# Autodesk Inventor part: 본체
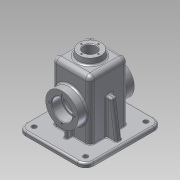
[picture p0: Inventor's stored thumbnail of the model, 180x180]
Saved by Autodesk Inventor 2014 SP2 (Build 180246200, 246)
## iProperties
Created: 2016-08
Part Number: 본체
Material: 알루미늄 6061
Document SubType Name: Modeling
Designer: user
Density: 2.71 g/cm^3
Appearance: 알루미늄 - 평지
Mass: 796.489 g
Surface Area: 912.85 cm^2
Volume: 293.907 cm^3
Author: user
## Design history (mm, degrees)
sketch "스케치1"
  geometry: L1 (-57.5, 65)-(57.5, 65); L2 (57.5, 65)-(57.5, -65); L3 (57.5, -65)-(-57.5, -65); L4 (-57.5, -65)-(-57.5, 65); L5 (-57.5, 65)-(57.5, -65); L6 (57.5, 65)-(-57.5, -65); 1 further point
  constraints: 12 end point, 2 midpoint, 2 parallel, 1 horizontal, 1 perpendicular
  dimensions: "d0" = 115 distance of L2.end L3.end; "d1" = 130 distance of L1.end L2.end
extrude "돌출1" new body sketch "스케치1" distance "d2" = 7; taper "d3" = 0 deg
fillet "모깎기1" dims "d4" = 14
sketch "스케치2"
  geometry: L1 (43.5, 65)-(-43.5, 65) reference; L2 (-57.5, 51)-(-57.5, -51) reference; L3 (-43.5, -65)-(43.5, -65) reference; L4 (57.5, -51)-(57.5, 51) reference; L5 (43.5, -60)-(-43.5, -60); L6 (-52.5, -51)-(-52.5, 51); L7 (-43.5, 60)-(43.5, 60); L8 (52.5, 51)-(52.5, -51); A1 r 14 centre (43.5, 51) between (57.5, 51) and (43.5, 65) reference; A2 r 14 centre (-43.5, 51) between (-43.5, 65) and (-57.5, 51) reference; A3 r 14 centre (-43.5, -51) between (-57.5, -51) and (-43.5, -65) reference; A4 r 14 centre (43.5, -51) between (43.5, -65) and (57.5, -51) reference; A5 r 9 centre (-43.5, -51) between (-52.5, -51) and (-43.5, -60); A6 r 9 centre (-43.5, 51) between (-43.5, 60) and (-52.5, 51); A7 r 9 centre (43.5, 51) between (52.5, 51) and (43.5, 60); A8 r 9 centre (43.5, -51) between (43.5, -60) and (52.5, -51); 1 further point
  constraints: 8 end point, 8 point on circle, 4 centre point, 7 other
  dimensions: "d5" = 5 distance between parallel lines of L5 L3
extrude "돌출2" join sketch "스케치2" distance "d6" = 3; taper "d7" = 0 deg
sketch "스케치3"
  geometry: L1 (-32.5, 32.5)-(32.5, 32.5); L2 (32.5, 32.5)-(32.5, -32.5); L3 (32.5, -32.5)-(-32.5, -32.5); L4 (-32.5, -32.5)-(-32.5, 32.5); L5 (-32.5, 32.5)-(32.5, -32.5); L6 (32.5, 32.5)-(-32.5, -32.5); 1 further point
  constraints: 12 end point, 2 midpoint, 2 parallel, 1 horizontal, 1 perpendicular
  dimensions: "d8" = 65 distance of L2.end L3.end; "d9" = 65 distance of L1.end L2.end
extrude "돌출3" join sketch "스케치3" distance "d10" = 100; taper "d11" = 0 deg
fillet "모깎기2" dims "d12" = 8
fillet "모깎기3" dims "d13" = 8
sketch "스케치4"
  geometry: L1 (-24.5, 107)-(24.5, 107) reference; L2 (-32.5, 7)-(-32.5, 99) reference; L3 (32.5, 99)-(32.5, 7) reference; L4 (27.5, -3)-(27.5, 99); L5 (24.5, 102)-(-24.5, 102); L6 (-27.5, 99)-(-27.5, -3); L7 (-51, -3)-(51, -3) reference; A1 r 8 centre (-24.5, 99) between (-24.5, 107) and (-32.5, 99) reference; A2 r 8 centre (24.5, 99) between (32.5, 99) and (24.5, 107) reference; A3 r 3 centre (24.5, 99) between (27.5, 99) and (24.5, 102); A4 r 3 centre (-24.5, 99) between (-24.5, 102) and (-27.5, 99); 1 further point
  constraints: 6 end point, 4 point on circle, 2 centre point, 2 point on line, 2 other
  dimensions: "d14" = 5 distance between parallel lines of L5 L1; "d15" = 5 distance between parallel lines of L6 L2; "d16" = 5 distance between parallel lines of L3 L4
extrude "돌출4" cut sketch "스케치4" stored distance "d17" = 55; taper "d18" = 0 deg
fillet "모깎기4" dims "d19" = 3
sketch "스케치5"
  geometry: L1 (68, -10)-(-19, -10) reference; C1 r 27.5 at (24.5, 45); 2 further points
  constraints: 1 centre point, 1 midpoint, 1 vertical alignment
  dimensions: "d20" = 55 diameter of C1; "d21" = 55 distance from line of L1 C1.centre
extrude "돌출5" join sketch "스케치5" distance "d22" = 15; taper "d23" = 0 deg
sketch "스케치7"
  geometry: C1 r 20 at (0, 0); 1 further point
  constraints: 1 centre point, 1 coincident
  dimensions: "d26" = 40 diameter of C1
extrude "돌출6" join sketch "스케치7" distance "d27" = 10; taper "d28" = -7 deg
sketch "스케치8"
  geometry: L1 (43.5, 7)-(57.5, 7) reference; L2 (-43.5, 7)-(43.5, 7) reference; L3 (-57.5, 7)-(-43.5, 7) reference; L4 (-49.5, 7)-(-41.068, 67); L5 (-57.5, 7)-(-57.5, 0) reference; L6 (43.5, -3)-(-43.5, -3) reference; L7 (-52.5, -3)-(-43.5, -3) reference; L8 (-32.5, 99)-(-32.5, 7) reference; L9 (-41.068, 67)-(-32.5, 67); 1 further point
  constraints: 4 end point, 2 point on line, 1 perpendicular
  dimensions: "d29" = 8 deg angle of L5 L4; "d30" = 8 distance of L3.start L4.start; "d31" = 70 vertical distance of L4.end L7.start
extrude "돌출7" join sketch "스케치8" stored distance "d32" = 10; taper "d33" = 0 deg
sketch "스케치10"
  geometry: L1 (3, 27.5)-(-3, 27.5); L2 (-3, 27.5)-(-3, 42.5); L3 (-3, 42.5)-(3, 42.5); L4 (3, 42.5)-(3, 27.5); L5 (24.5, 27.5)-(-24.5, 27.5) reference; 2 further points
  constraints: 8 end point, 2 midpoint, 2 parallel, 1 horizontal, 1 perpendicular, 1 vertical alignment
  dimensions: "d37" = 15 distance of L1.end L2.end; "d38" = 6 distance of L2.end L3.end
extrude "돌출9" join sketch "스케치10" stored distance "d39" = 6; taper "d40" = 0 deg
fillet "모깎기5" dims "d41" = 3
hole "구멍1" diameter "d44" = 21; stored, may be unused: countersink angle "d48" = 90 deg, drill point angle "d50" = 0 deg; dims "d42" = 10, "d43" = 10, "d45" = 6, "d46" = 4, "d47" = 2, "d49" = 8
fillet "모깎기6" dims "d51" = 3
fillet "모깎기7" dims "d52" = 3
hole "구멍2" diameter "d55" = 35; stored, may be unused: countersink angle "d59" = 90 deg, drill point angle "d61" = 0 deg; dims "d53" = 10, "d54" = 10, "d56" = 6, "d57" = 4, "d58" = 2, "d60" = 17
hole "구멍3" diameter "d64" = 35; stored, may be unused: countersink angle "d68" = 90 deg, drill point angle "d70" = 0 deg; dims "d62" = 10, "d63" = 10, "d65" = 6, "d66" = 4, "d67" = 2, "d69" = 17
hole "구멍4" diameter "d73" = 30; stored, may be unused: countersink angle "d77" = 90 deg, drill point angle "d79" = 0 deg; dims "d71" = 10, "d72" = 10, "d74" = 6, "d75" = 4, "d76" = 2, "d78" = 17
fillet "모깎기9" dims "d81" = 3
fillet "모깎기10" dims "d82" = 3
fillet "모깎기11" dims "d83" = 3
fillet "모깎기12" dims "d84" = 3
hole "구멍5" diameter "d87" = 8; stored, may be unused: countersink angle "d91" = 90 deg, drill point angle "d93" = 0 deg; dims "d85" = 10, "d86" = 10, "d88" = 6, "d89" = 4, "d90" = 2, "d92" = 17
hole "구멍6" diameter "d96" = 8; stored, may be unused: countersink angle "d100" = 90 deg, drill point angle "d102" = 0 deg; dims "d94" = 10, "d95" = 10, "d97" = 6, "d98" = 4, "d99" = 2, "d101" = 17
hole "구멍7" diameter "d105" = 8; stored, may be unused: countersink angle "d109" = 90 deg, drill point angle "d111" = 0 deg; dims "d103" = 10, "d104" = 10, "d106" = 6, "d107" = 4, "d108" = 2, "d110" = 17
hole "구멍8" diameter "d114" = 8; stored, may be unused: countersink angle "d118" = 90 deg, drill point angle "d120" = 0 deg; dims "d112" = 10, "d113" = 10, "d115" = 6, "d116" = 4, "d117" = 2, "d119" = 17
fillet "모깎기13" dims "d121" = 3
sketch "스케치11"
  geometry: 2 further points
  constraints: 1 vertical alignment
  dimensions: "d122" = 14.5 distance of point (0, 14.5) point (0, 0)
hole "구멍9" sketch "스케치11" at (0, 14.5) diameter "d123" = 2.459; stored, may be unused: countersink angle "d127" = 90 deg, drill point angle "d129" = 118 deg; dims "d124" = 7, "d125" = 4, "d126" = 2, "d128" = 9
sketch "스케치12"
  geometry: C1 r 15 at (0, 0) reference; 2 further points
  constraints: 1 horizontal alignment
  dimensions: "d133" = 21 distance of point (21, 0) C1.centre
hole "구멍10" sketch "스케치12" at (21, 0) diameter "d134" = 3.242; stored, may be unused: countersink angle "d138" = 90 deg, drill point angle "d140" = 118 deg; dims "d135" = 8, "d136" = 4, "d137" = 2, "d139" = 10
fillet "모깎기14" dims "d144" = 0.3
sketch "스케치13"
  geometry: L1 (57, 0)-(57, 92) reference; L2 (43.272, -18)-(5.728, -18) reference; 2 further points
  constraints: 1 other
  dimensions: "d145" = 32.5 distance from line of point (24.5, 8) L1; "d146" = 26 distance from line of point (24.5, 8) L2
feature "엠보싱1" sketch "스케치13" dims "d147" = 0.5, "d148" = 0
fillet "모깎기15" dims "d149" = 3
fillet "모깎기16" dims "d150" = 3
fillet "모깎기17" dims "d151" = 1
chamfer "모따기1" distance "d152" = 1; stored, may be unused: second distance "d153" = 2, angle "d154" = 45 deg
chamfer "모따기2" distance "d155" = 1; stored, may be unused: second distance "d156" = 2, angle "d157" = 45 deg
node "솔리드1"
mirror "대칭1"
mirror "대칭2"
mirror "대칭4"
pattern_circular "원형 패턴1" dims angle "d131" = 360 deg
pattern_circular "원형 패턴2" dims angle "d142" = 360 deg
mirror "대칭5"
node "투영된 루프1"
